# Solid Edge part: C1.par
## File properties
Author: edge
Template: Jis Part.par
Last saved by: edge
Revision: 11
Application: Solid Edge
Username: edge
文書内容のタイプ: 0
Accuracy: 0.990
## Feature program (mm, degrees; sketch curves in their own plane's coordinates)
sketch for "unnamed Protrusion 1" plane through (0, 0, 0) normal (0, 0, 1) x-axis (1, 0, 0)
  line (40, -40) -> (-40, -40)
  line (-40, -40) -> (-40, 40)
  line (-40, 40) -> (40, 40)
  line (40, 40) -> (40, -40)
  dimension (linear) = 40
  dimension (linear) = 40
extrude "unnamed Protrusion 1" add finite 60 along +normal
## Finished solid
Body 1: solid body, 6 faces, 12 edges, 8 vertices.
  Faces by surface: plane 6
  Edges by curve: line 12
Bounding box of the edges (mm): 80.000 x 80.000 x 60.000, from (-40, -40, 0) to (40, 40, 60).
Planar faces by outward normal: +x 1, +y 1, +z 1, -x 1, -y 1, -z 1
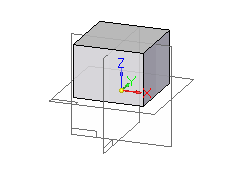
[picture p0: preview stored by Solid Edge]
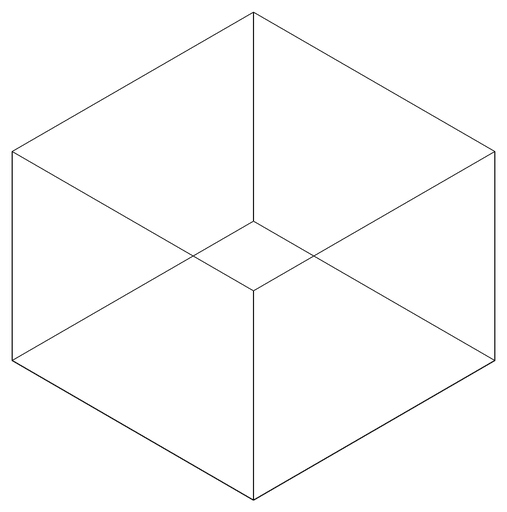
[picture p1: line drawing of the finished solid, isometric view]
